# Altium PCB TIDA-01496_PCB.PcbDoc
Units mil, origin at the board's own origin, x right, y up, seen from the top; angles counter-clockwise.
Board outline 2187.5 x 2187.5 mil, 2 copper layers (Top Layer, Bottom Layer), stack 62 mil thick; 30 components, 21 nets, 107 pads, 21 vias.
Unrouted connection lines stored in the file: 1.
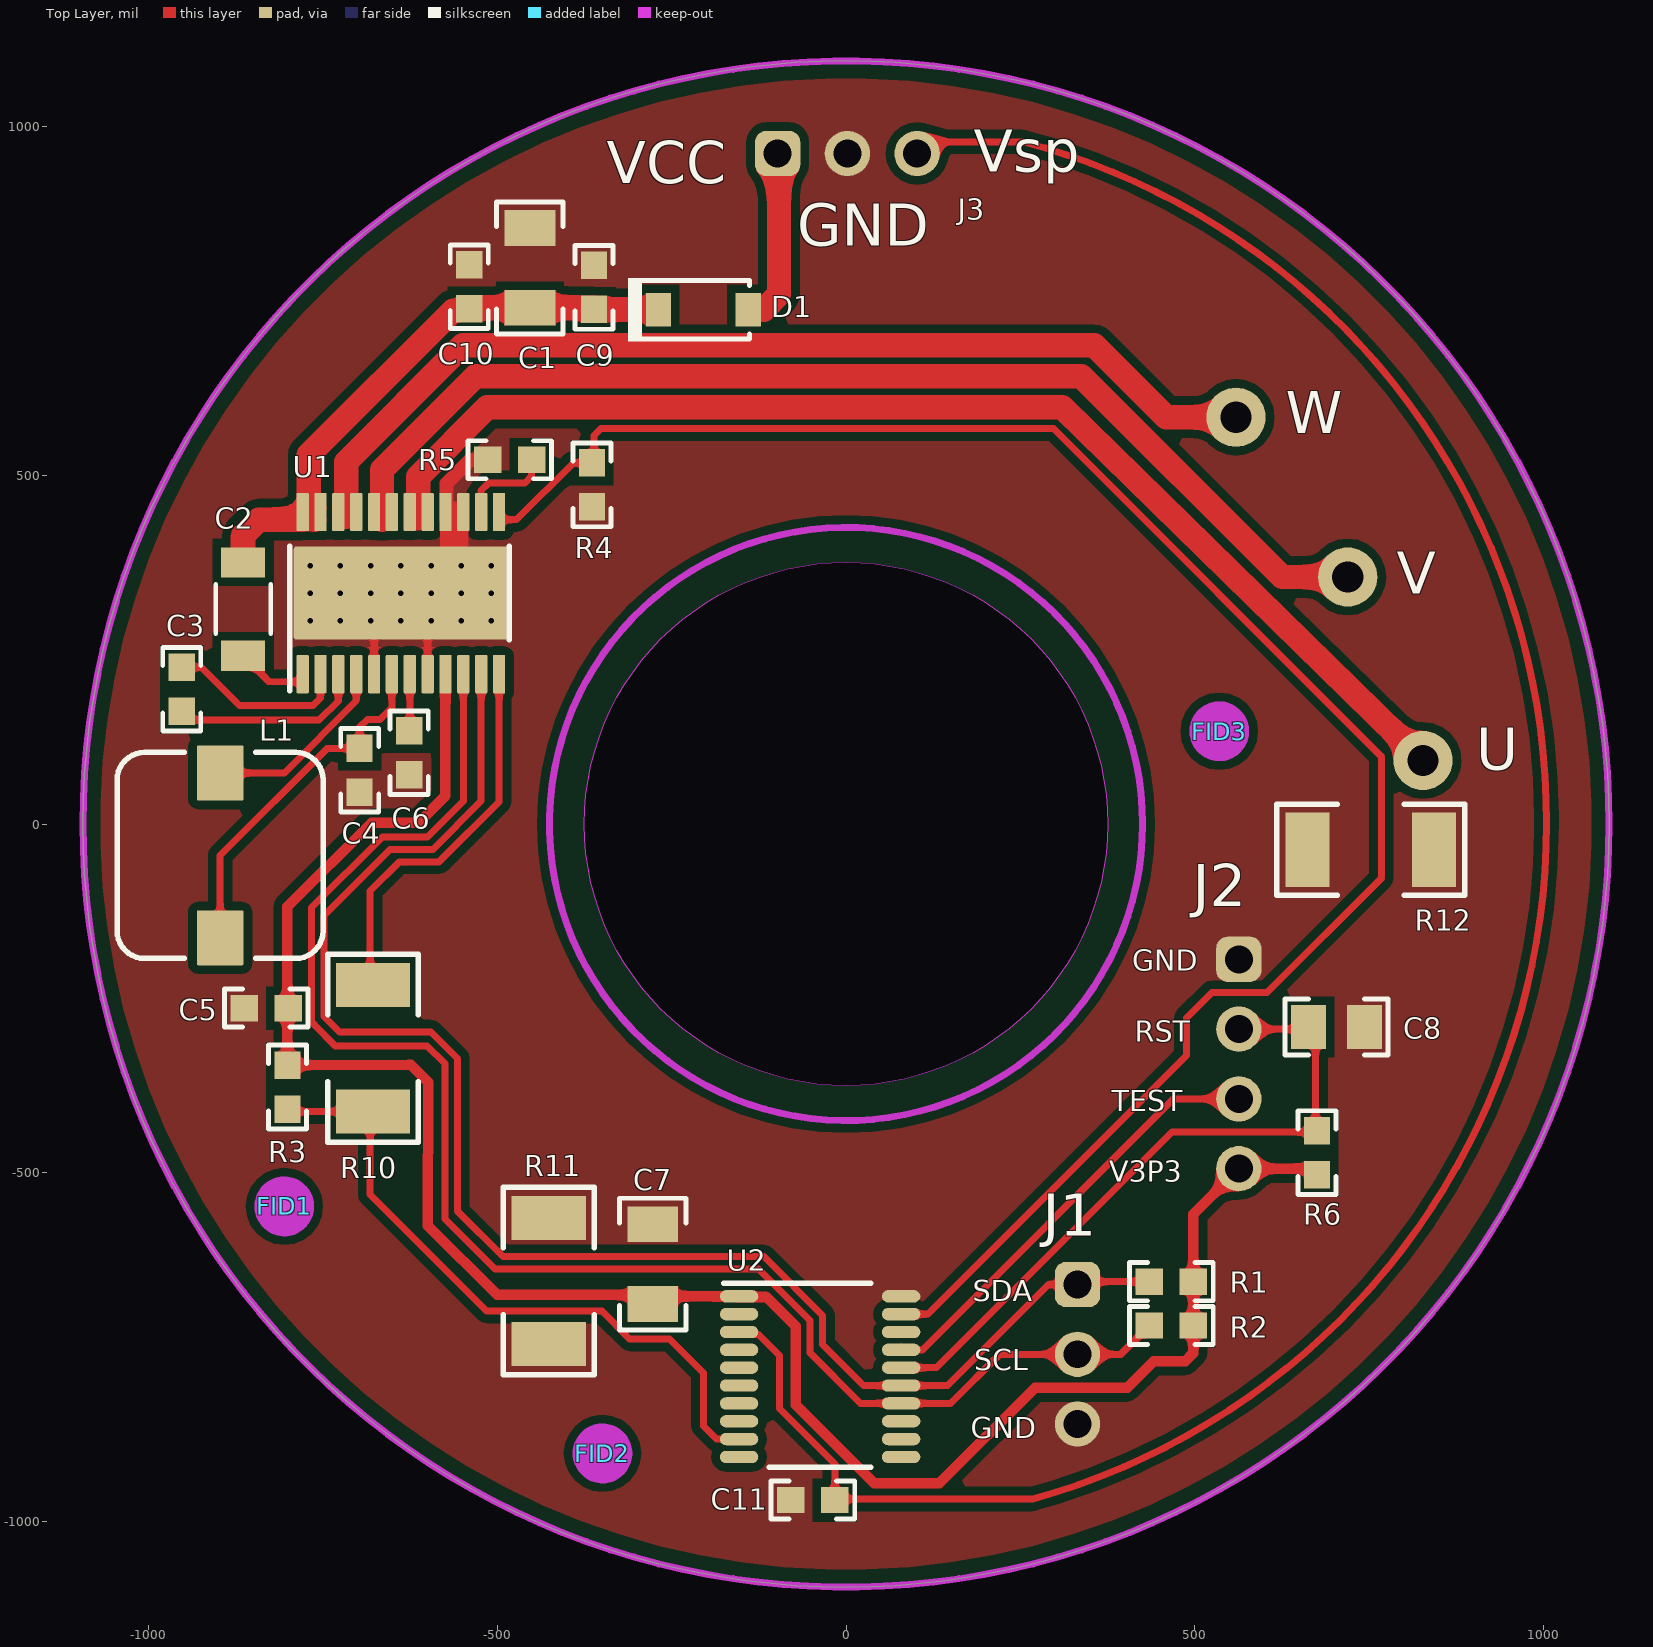
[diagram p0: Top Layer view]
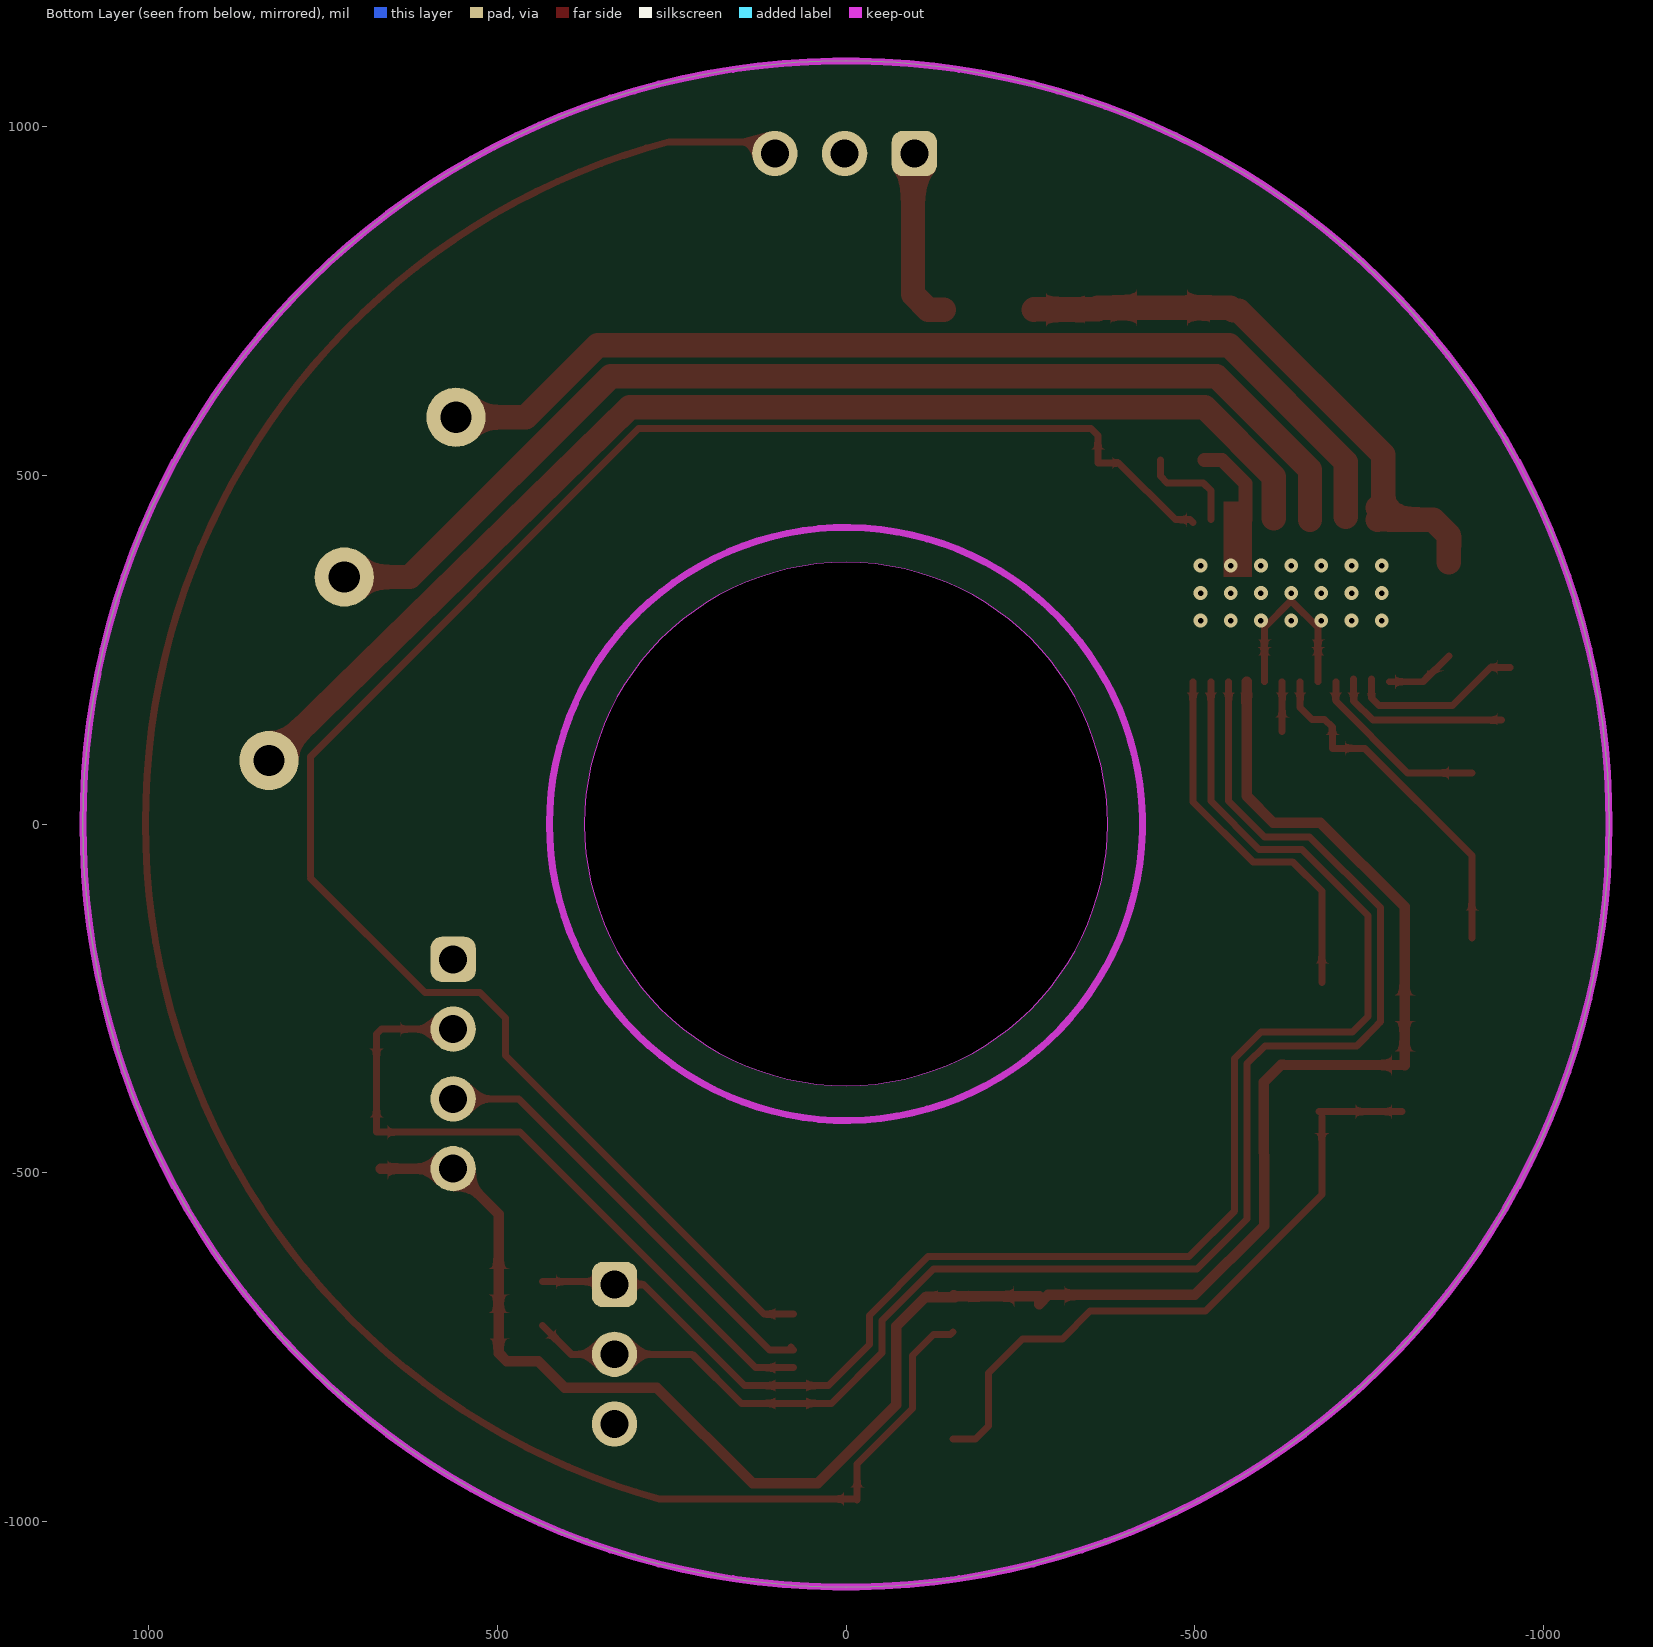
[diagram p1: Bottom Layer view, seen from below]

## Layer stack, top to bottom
Top Solder: solder mask 0.4, Solder Resist, Dk 3.5
Top Layer: signal copper 2.8
Dielectric1: core 59.2, FR-4, Dk 4.8
Bottom Layer: signal copper (thickness not stored)

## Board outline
0,-1093.75 cw(c0,0) -1093.75,0 cw(c0,0) 0,1093.75 cw(c0,0) 1093.75,0 cw(c0,0)
cut-out: 0,375 cw(c0,0) 375,0 cw(c0,0) 0,-375 cw(c0,0) -375,0 cw(c0,0)

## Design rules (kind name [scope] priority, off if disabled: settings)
AcuteAngle [All] p1: minimum=4.50000000000000E+0001 checktracksonly=FALSE
AssemblyTestPointUsage [All] p1: valid=2
BoardOutlineClearance BoardOutlineClearance_MountingHoles [OnCopper and InComponentClass('Mounting Holes')] p1: gap=40 ignorepadtopadclearanceinfootprint=FALSE
BoardOutlineClearance BoardOutlineClearance_Poly [OnCopper and IsPoly] p2: gap=25 ignorepadtopadclearanceinfootprint=FALSE
BoardOutlineClearance [OnCopper and Not InComponentClass('Logo') and not InComponentClass('FiducialMark') and not InRegion(1000,500,4000,800) and not InPoly] p3: gap=40 ignorepadtopadclearanceinfootprint=FALSE
Clearance Clearance_Keepouts [((IsTrack Or IsArc) And Not InPoly) And IsFree and IsKeepOut vs ((IsTrack Or IsArc) And Not InPoly) And IsFree and IsKeepOut] p1: gap=0 ignorepadtopadclearanceinfootprint=FALSE
Clearance Clearance_Poly [InPolygon] p2: gap=12 ignorepadtopadclearanceinfootprint=FALSE except(0: Arc-Hole Track-Hole SMDPad-Hole THPad-Hole Via-Hole Fill-Hole Poly-Hole Region-Hole Text-Hole)
Clearance [All] p3: gap=7 ignorepadtopadclearanceinfootprint=FALSE except(0: Arc-Hole Track-Hole SMDPad-Hole THPad-Hole Via-Hole Fill-Hole Poly-Hole Region-Hole Text-Hole)
ComponentClearance ComponentClearance_MountingHoles_FiducialMarks [InComponentClass('Mounting Holes') vs InComponentClass('FiducialMark')] p1: gap=50 collisioncheckmode=3 verticalgap=10 showdistances=FALSE
ComponentClearance ComponentClearance_Shunt [InComponentClass('Header') vs InComponentClass('Shunt')] p2: gap=0 collisioncheckmode=3 verticalgap=0 showdistances=FALSE
ComponentClearance ComponentClearance_Logo [InComponentClass('Logo')] p3: gap=50 collisioncheckmode=3 verticalgap=10 showdistances=FALSE
ComponentClearance ComponentClearance_ScrewToNut [(HasFootprint('NY PMS 440 0025 PH')) vs (HasFootprint('Keystone_1902C'))] p4: gap=5 collisioncheckmode=3 verticalgap=10 showdistances=FALSE
ComponentClearance ComponentClearance_MountingHoles [InComponentClass('Mounting Holes')] p5: gap=250 collisioncheckmode=3 verticalgap=100000 showdistances=FALSE
ComponentClearance ComponentClearance_SmallPassives [HasFootprint('0201*') or HasFootprint('0402*') or HasFootprint('0508') or HasFootprint('0603*') or HasFootprint('0612') or HasFootprint('0805*') or HasFootprint('0815*') or HasFootprint('0830*') or HasFootprint('1206*') or HasFootprint('1210*') or HasFootprint('1808*') or HasFootprint('1812*') or HasFootprint('1825*') or HasFootprint('2010*') or HasFootprint('2220*') or HasFootprint('2225*') or HasFootprint('2512*') or HasFootprint('2728*') or HasFootprint('3518*') vs HasFootprint('0201*') or HasFootprint('0402*') or HasFootprint('0508') or HasFootprint('0603*') or HasFootprint('0612') or HasFootprint('0805*') or HasFootprint('0815*') or HasFootprint('0830*') or HasFootprint('1206*') or HasFootprint('1210*') or HasFootprint('1808*') or HasFootprint('1812*') or HasFootprint('1825*') or HasFootprint('2010*') or HasFootprint('2220*') or HasFootprint('2225*') or HasFootprint('2512*') or HasFootprint('2728*') or HasFootprint('3518*')] p6: gap=14.96 collisioncheckmode=3 verticalgap=10 showdistances=FALSE
ComponentClearance ComponentClearance_THtoSMT [IsThruComponent vs IsSMTComponent] p7: gap=40 collisioncheckmode=3 verticalgap=30 showdistances=FALSE
ComponentClearance ComponentClearance_THtoTH [IsThruComponent vs IsThruComponent] p8: gap=30 collisioncheckmode=3 verticalgap=30 showdistances=FALSE
ComponentClearance [All] p9: gap=30 collisioncheckmode=3 verticalgap=10 showdistances=FALSE
DiffPairsRouting [All] p1: maxlimit=100 minlimit=10 mostfreqgap=10 toplayer_minwidth=15 toplayer_maxwidth=15 toplayer_prefwidth=15 bottomlayer_minwidth=15 bottomlayer_maxwidth=15 bottomlayer_prefwidth=15 maxuncoupledlength=1000
FabricationTestPointUsage TestPointUsage [All] p1: valid=2 allowmultiple=FALSE
FabricationTestpoint Testpoint [All] p1: side=3 testpointundercomponent=TRUE minsize=40 maxsize=100 preferedsize=60 minholesize=0 maxholesize=40 preferedholesize=32 testpointgrid=1 allowsidetop=TRUE allowsidebottom=TRUE usegrid=TRUE gridtolerance=0.01
FanoutControl Fanout_LCC [IsLCC] p1: bgadir=Out bgaviamode=Centered fanoutstyle=Auto fanoutdirection=Alternating viagrid=1 // Fanout_LCC (Default Rule)
FanoutControl Fanout_BGA [IsBGA] p2: bgadir=Out bgaviamode=Centered fanoutstyle=Auto fanoutdirection=Alternating viagrid=1 // Fanout_BGA (Default Rule)
FanoutControl Fanout_Default [All] p4: bgadir=Out bgaviamode=Centered fanoutstyle=Auto fanoutdirection=Alternating viagrid=1 // Fanout_Default (Default Rule)
FanoutControl Fanout_Small [(CompPinCount < 5)] p5: bgadir=Out bgaviamode=Centered fanoutstyle=Auto fanoutdirection=OutThenIn viagrid=1 // Fanout_Small (Default Rule)
HoleSize [All] p1: absolutevalues=TRUE maxlimit=251 minlimit=7.87 maxpercent=80.000 minpercent=20.000
MinimumAnnularRing MinimumAnnularRing_ThermalPadVias [IsVia and InAnyComponent] p1: minimumring=5.91
MinimumAnnularRing [All] p2: minimumring=8
MinimumSolderMaskSliver MinimumSolderMaskSliver_Logo [InComponentClass('Logo') vs InComponentClass('Logo')] p1: minsoldermaskwidth=0.7
MinimumSolderMaskSliver [All] p2: minsoldermaskwidth=3.9
PlaneConnect [All] p1: planeconnectstyle=Relief reliefexpansion=10 reliefentries=4 reliefconductorwidth=10 reliefairgap=10
PolygonConnect PolygonConnect_4 [All vs IsNamedPolygon('TOP_LAYER_GND_P008')] p1: connectstyle=Direct reliefconductorwidth=10 reliefentries=4 polygonreliefangle="90 Angle" airgapwidth=10
PolygonConnect PolygonConnect_3 [All vs IsNamedPolygon('TOP_LAYER_GND_P008')] p2: connectstyle=Direct reliefconductorwidth=10 reliefentries=4 polygonreliefangle="90 Angle" airgapwidth=10
PolygonConnect PolygonConnect_2 [All vs IsNamedPolygon('TOP_LAYER_GND_P008')] p3: connectstyle=Direct reliefconductorwidth=10 reliefentries=4 polygonreliefangle="90 Angle" airgapwidth=10
PolygonConnect PolygonConnect_1 [All vs IsNamedPolygon('TOP_LAYER_GND_P008')] p4: connectstyle=Direct reliefconductorwidth=10 reliefentries=4 polygonreliefangle="90 Angle" airgapwidth=10
PolygonConnect [All] p5: connectstyle=Relief reliefconductorwidth=10 reliefentries=4 polygonreliefangle="90 Angle" airgapwidth=10
RoutingVias ThermalPadVias [IsVia and InAnyComponent] p1: holewidth=7.87 width=19.68 viastyle="Through Hole" minholewidth=7.87 minwidth=19.68 maxholewidth=12.99 maxwidth=23.62
RoutingVias [All] p2: holewidth=16 width=34 viastyle="Through Hole" minholewidth=7.87 minwidth=26 maxholewidth=40 maxwidth=65
SilkToBoardRegionClearance [Not ((IsComment or IsDesignator) And (Hide <> 'False')) and not InRegion(1000,500,4000,800)] p1:
SilkToSilkClearance SilkToSilkClearance_Pb-FreeLogo [(HasFootprint('Pb-Free_Overlay_Medium') OR HasFootprint('Pb-Free_Overlay_Small')) vs (HasFootprint('Pb-Free_Overlay_Medium') OR HasFootprint('Pb-Free_Overlay_Small'))] p1: silktosilkclearance=0
SilkToSilkClearance [All] p2: silktosilkclearance=4
SilkToSolderMaskClearance SilkToComponentPadClearance [(IsPad or IsFill or IsRegion) and InAnycomponent] p1: minsilkscreentomaskgap=3.5 clearancetoexposedcopper=TRUE
SilkToSolderMaskClearance "Silk to Solder Mask Opening" [All] p2: minsilkscreentomaskgap=4 clearancetoexposedcopper=FALSE
SolderMaskExpansion [All] p1: expansion=1.97
Width [All] p1: maxlimit=100 minlimit=6 preferedwidth=10 checkconnectedcopper=TRUE
15 further rules are at their usual default settings.

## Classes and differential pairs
component class Header: J1 J2 J3
component class TIDA-01496_Hardware: !PCB FID1 FID2 FID3
component class FiducialMark: FID1 FID2 FID3
component class TIDA-01496: C1 C2 C3 C4 C5 C6 C7 C8 C9 C10 C11 D1 J1 J2 J3 L1 R1 R2 R3 R4 R5 R6 R10 R11 R12 U1 U2

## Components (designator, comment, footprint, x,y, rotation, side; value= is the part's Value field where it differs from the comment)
C1 "Capacitor" 1206 -453,797 r90 top value=10uF
C2 "Capacitor" 1206_180 -864,308 r270 top value=0.1uF
C3 "Capacitor" 0603 -952,193 r270 top value=0.01uF
C4 "Capacitor" 0603 -697,77 r270 top value=10uF
C5 "Capacitor" 0603 -831,-264 r0 top value=1uF
C6 "Capacitor" 0603 -626,102 r90 top value=1uF
C7 "Capacitor" 1206 -277,-630.91 r90 top value=0.1uF
C8 "Capacitor" 0805_HV 703,-291 r0 top value=2200pF
C9 "Capacitor" 0603 -361,769 r90 top value=0.1uF
C10 "Capacitor" 0603 -540,770 r90 top value=10uF
C11 "Capacitor" 0603 -47.5,-969 r180 top value=470pF
D1 "DIODE_SCHOTTKY" SOD-123FL -204.47,737 r0 top value=30V
FID1 "Fiducial" Fiducial6.4-20 -805,-548 r0 top
FID2 "Fiducial" Fiducial6.4-20 -349,-902 r0 top
FID3 "Fiducial" Fiducial6.4-20 535.01,132.9 r0 top
J1 "TSW-103-07-G-S" TSW-103-07-G-S 331.8,-760 r270 top
J2 "TSW-104-07-G-S" TSW-104-07-G-S 563,-344 r270 top
J3 "TSW-103-07-G-S" TSW-103-07-G-S 2,961 r0 top
L1 "784777470" WE-PDA_7345 -897,-45 r90 top value=47uH
R1 "Resistor" 0603 466.31,-656 r0 top value=4.75k
R2 "Resistor" 0603 466.31,-719 r0 top value=4.75k
R3 "Resistor" 0603 -800.5,-376.99 r90 top value=4.75k
R4 "Resistor" 0603 -364,486 r90 top value=4.75k
R5 "Resistor" 0603 -482,522 r0 top value=4.75k
R6 "Resistor" 0603 675,-471 r270 top value=47k
R10 "Resistor" 2010 -678,-321.55 r270 top value=0
R11 "Resistor" 2010 -426,-655 r90 top value=0
R12 "Resistor" 2010 752,-37 r180 top value=0
U1 "DRV10983SQPWPRQ1" PWP0024B_N -638,331 r90 top
U2 "MSP430G2553IPW0RQ1" PW0020A_N -37.14,-792.02 r0 top

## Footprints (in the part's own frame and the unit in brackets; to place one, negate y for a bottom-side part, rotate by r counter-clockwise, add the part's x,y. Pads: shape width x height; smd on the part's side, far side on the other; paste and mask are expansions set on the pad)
0603 [mm] "0603 from SM-752 data"
  rect 1x0.95 smd: 1(-0.8,0) 2(0.8,0)
  silkscreen extent -1.52,-0.69 1.52,0.69, body extent -0.87,-0.47 0.87,0.47, height 1
0805_HV [mil] "0805 with 30mil clearance between pads"
  rect 50x63 smd: 1(-40,0) 2(40,0)
  silkscreen extent -74,-40 74,40, body extent -43,-29 43,29, height 57
1206 [mm] "1206 from SM-752 data"
  rect 1.3x1.85 smd: 1(-1.45,0) 2(1.45,0)
  silkscreen extent -2.4,-1.21 2.4,1.21, body extent -1.7,-0.9 1.7,0.9, height 1.35
1206_180 [mm] "1206_180"
  rect 1.1x1.6 smd: 1(-1.7,0) 2(1.7,0)
  silkscreen extent -0.9,-1 0.9,1, body extent -1.75,-0.95 1.75,0.95, height 1.8
2010 [mm] "Chip Capacitor, Body 5.08x2.54mm, IPC Medium Density"
  rect 1.6x2.7 smd: 1(-2.3,0) 2(2.3,0)
  silkscreen extent -3.42,-1.65 3.42,1.65, body extent -2.73,-1.45 2.73,1.45, height 1.66
Fiducial6.4-20 [mil]
  round 25 smd mask+26.87: 1(0,0)
  Top Layer keep-out circle w46.37: c0,0 r19.68
PW0020A_N [mm] "TSOP, 20-Leads, Body 6.5x4.4mm, Pitch 0.65mm, IPC Medium Density"
  oval 1.4x0.45 smd: 1(-2.95,2.925) 2(-2.95,2.275) 3(-2.95,1.625) 4(-2.95,0.975) 5(-2.95,0.325) 6(-2.95,-0.325) 7(-2.95,-0.975) 8(-2.95,-1.625) 9(-2.95,-2.275) 10(-2.95,-2.925) 11(2.95,-2.925) 12(2.95,-2.275) 13(2.95,-1.625) 14(2.95,-0.975) 15(2.95,-0.325) 16(2.95,0.325) 17(2.95,0.975) 18(2.95,1.625) 19(2.95,2.275) 20(2.95,2.925)
  Top Overlay keep-out lines w0.2: -1.85,-3.3 1.85,-3.3
  silkscreen extent -3.5,-3.3 1.85,3.4, body extent -3.21,-3.25 3.21,3.25, height 1
PWP0024B_N [mm] "TSOP, 24-Leads, Body 7.9x4.5mm (max), Pitch 0.65mm, IPC Medium Density"
  rrect22% 1.4x0.45 smd: 1(-2.95,3.575) 2(-2.95,2.925) 3(-2.95,2.275) 4(-2.95,1.625) 5(-2.95,0.975) 6(-2.95,0.325) 7(-2.95,-0.325) 8(-2.95,-0.975) 9(-2.95,-1.625) 10(-2.95,-2.275) 11(-2.95,-2.925) 12(-2.95,-3.575) 13(2.95,-3.575) 14(2.95,-2.925) 15(2.95,-2.275) 16(2.95,-1.625) 17(2.95,-0.975) 18(2.95,-0.325) 19(2.95,0.325) 20(2.95,0.975) 21(2.95,1.625) 22(2.95,2.275) 23(2.95,2.925) 24(2.95,3.575)
  rrect6% 3.4x7.8 smd paste-2 mask-2: 25(0,0)
  rrect4% 2.4x5.16 on Top Paste: 25(0,0)
  rrect4% 2.4x5.16 on Top Solder: 25(0,0)
  silkscreen extent -3.55,-3.95 1.7,4.05, body extent -3.21,-3.9 3.21,3.9, height 1.2
SOD-123FL [mm] "Copied from SOD-123"
  rect 0.915x1.22 smd: 1(-1.637,0) 2(1.637,0)
  silkscreen extent -2.74,-1.16 1.68,1.16, body extent -1.9,-0.9 1.9,0.9, height 1
TSW-103-07-G-S [mm] "Samtec 100mil, 1x3, 230 mil above insulator"
  rrect50% 1.65x1.65 hole 1.016: 1(-2.54,0)
  round 1.65 hole 1.016: 2(0,0) 3(2.54,0)
  body extent -3.81,-1.27 3.81,1.27, height 8.38
TSW-104-07-G-S [mm] "Samtec 100mil, 1x4, 230 mil above insulator"
  rrect50% 1.65x1.65 hole 1.016: 1(-3.81,0)
  round 1.65 hole 1.016: 2(-1.27,0) 3(1.27,0) 4(3.81,0)
  body extent -5.08,-1.27 5.08,1.27, height 8.38
WE-PDA_7345 [mm] "SMD, 2-Leads, Body 7.3x7.3mm"
  rrect6% 2x1.7 smd: 1(-3,0) 2(3,0)
  silkscreen extent -3.75,-3.75 3.75,3.75, body extent -3.65,-3.65 3.65,3.65, height 4.05

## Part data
C1: library part CMP-0008785-2, "CAP, CERM, 10 uF, 50 V, +/- 20%, X5R, AEC-Q200 Grade 3, 1206", Cap_Case=1206, Manufacturer=TDK, PartNumber=CGA5L3X5R1H106M160AB, Supplier Part Number 1=445-12883-1-ND, TempCo=X5R, Tolerance_%=20%, Value1=Unknown, Value2=50V, ValueDisplayed=10uF
C2: library part CMP-0064950-2, "CAP, CERM, 0.1 uF, 25 V,+/- 5%, C0G/NP0, 1206", Cap_Case=1206, Manufacturer=MuRata, PartNumber=GRM31C5C1E104JA01L, Supplier Part Number 1=490-1767-1-ND, TempCo=C0G/NP0, Tolerance_%=5%, Value1=Unknown, Value2=25V, ValueDisplayed=0.1uF
C3: library part CMP-0006854-4, "CAP, CERM, 0.01 uF, 50 V, +/- 10%, X7R, 0603", Cap_Case=0603, Manufacturer=Kemet, PartNumber=C0603C103K5RACTU, Supplier Part Number 1=399-1091-1-ND, TempCo=X7R, Tolerance_%=10%, Value1=Unknown, Value2=50V, ValueDisplayed=0.01uF
C4: library part CMP-0007023-4, "CAP, CERM, 10 uF, 10 V, +/- 10%, X6S, 0603", Cap_Case=0603, Manufacturer=TDK, PartNumber=C1608X6S1A106M080AC, Supplier Part Number 1=445-9019-1-ND, TempCo=X6S, Tolerance_%=10%, Value1="0.004639 ohm", Value2=10V, ValueDisplayed=10uF
C5 C6: library part CMP-0007302-5, "CAP, CERM, 1 uF, 6.3 V, +/- 10%, X5R, 0603", Cap_Case=0603, Manufacturer=MuRata, PartNumber=GRM188R60J105KA01D, Supplier Part Number 1=490-1550-1-ND, TempCo=X5R, Tolerance_%=10%, Value1=Unknown, Value2=6.3V, ValueDisplayed=1uF
C7: library part CMP-0008586-2, "CAP, CERM, 0.1 uF, 50 V, +/- 10%, X7R, 1206", Cap_Case=1206, Manufacturer=Kemet, PartNumber=C1206C104K5RACTU, Supplier Part Number 1=399-1249-1-ND, TempCo=X7R, Tolerance_%=10%, Value1="0.059 ohm", Value2=50V, ValueDisplayed=0.1uF
C8: library part CMP-0007601-2, "CAP, CERM, 2200 pF, 50 V, +/- 5%, C0G/NP0, 0805", Cap_Case=0805, Manufacturer=AVX, PartNumber=08055A222JAT2A, Supplier Part Number 1=478-1330-1-ND, TempCo=C0G/NP0, Tolerance_%=5%, Value1="0.08 ohm", Value2=50V, ValueDisplayed=2200pF
C9: library part CMP-0006802-4, "CAP, CERM, 0.1 uF, 50 V, +/- 10%, X7R, 0603", Cap_Case=0603, Manufacturer=AVX, PartNumber=06035C104KAT2A, Supplier Part Number 1=478-5052-1-ND, TempCo=X7R, Tolerance_%=10%, Value1=Unknown, Value2=50V, ValueDisplayed=0.1uF
C10: library part CMP-0007007-5, "CAP, CERM, 10 uF, 25 V, +/- 20%, X5R, 0603", Cap_Case=0603, Manufacturer=TDK, PartNumber=C1608X5R1E106M080AC, Supplier Part Number 1=445-9015-1-ND, TempCo=X5R, Tolerance_%=20%, Value1="0.004639 ohm", Value2=25V, ValueDisplayed=10uF
C11: library part CMP-0006790-4, "CAP, CERM, 470 pF, 50 V, +/- 5%, C0G/NP0, 0603", Cap_Case=0603, Manufacturer=AVX, PartNumber=06035A471JAT2A, Supplier Part Number 1=478-1183-1-ND, TempCo=C0G/NP0, Tolerance_%=5%, Value1="0.063 ohm", Value2=50V, ValueDisplayed=470pF
D1: library part CMP-0028770-1, "Diode, Schottky, 30 V, 2 A, AEC-Q101, SOD-123FL", Manufacturer="ON Semiconductor", PartNumber=MBR230LSFT1G, Supplier Part Number 1=MBR230LSFT1GOSCT-ND, Value1=2A, Value2=0.43V
FID1 FID2 FID3: library part CMP-0077181-1, "Fiducial mark.  There is nothing to buy or mount.", Manufacturer=N/A
J1 J3: library part CMP-0075407-2, "Header, 100mil, 3x1, Gold, TH", Color=Black, Current_A=6.3A, Manufacturer=Samtec, Supplier Part Number 1=SAM1029-03-ND, Voltage_V=550V
J2: library part CMP-0075409-2, "Header, 100mil, 4x1, Gold, TH", Color=Black, Current_A=6.3A, Manufacturer=Samtec, Supplier Part Number 1=SAM1029-04-ND, Voltage_V=550V
L1: library part CMP-0078174-2, "Inductor, Shielded, Ferrite, 47 µH, 1.15 A, .3 ohm, AEC-Q200 Grade 1, SMD", Manufacturer="Wurth Elektronik", Supplier Part Number 1=732-6761-1-ND, Value1=".3 ohm", Value2=1.15A, ValueDisplayed=47µH
R1 R2 R3 R4 R5: library part CMP-0022456-4, "RES, 4.75 k, 1%, 0.1 W, AEC-Q200 Grade 0, 0603", Manufacturer=Vishay-Dale, PartNumber=CRCW06034K75FKEA, Power_W=100mW, Supplier Part Number 1=541-4.75KHCT-ND, TempCo="100 ppm/C", Tolerance_%=1%, Value2=0.1W, Value_Code=4k75, ValueDisplayed=4.75k
R6: library part CMP-0025814-4, "RES, 47 k, 5%, 0.1 W, AEC-Q200 Grade 0, 0603", Manufacturer=Vishay-Dale, PartNumber=CRCW060347K0JNEA, Power_W=100mW, Supplier Part Number 1=541-47KGCT-ND, TempCo="200 ppm/C", Tolerance_%=5%, Value2=0.1W, Value_Code=47k0, ValueDisplayed=47k
R10 R11 R12: library part CMP-0016044-3, "RES, 0, 5%, 0.75 W, AEC-Q200 Grade 0, 2010", Manufacturer=Vishay-Dale, PartNumber=CRCW20100000Z0EF, Power_W=750mW, Supplier Part Number 1=541-0.0WCT-ND, TempCo=ppm/C, Tolerance_%=5%, Value2=0.75W, Value_Code=0000, ValueDisplayed=0
U1: library part CMP-0065210-4, "Automotive, Three-Phase, Sensorless BLDC Motor Driver, PWP0024B (TSSOP-24)", Alternate Manufacturer="Texas Instruments"
U2: library part CMP-0081287-1, "MSP430(TM) Ultra-Low-Power Microcontrollers for Automotive Applications, PW0020A (TSSOP-20)", Alternate Manufacturer="Texas Instruments"

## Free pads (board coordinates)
  round 85 hole 45: 5(559,583) 6(719,354) 7(827,91)

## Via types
v1: diameter 19.68, hole 7.87, Top Layer to Bottom Layer, 15 vias
v2: diameter 19.68, hole 7.87, Top Layer to Bottom Layer, tented both sides, 6 vias

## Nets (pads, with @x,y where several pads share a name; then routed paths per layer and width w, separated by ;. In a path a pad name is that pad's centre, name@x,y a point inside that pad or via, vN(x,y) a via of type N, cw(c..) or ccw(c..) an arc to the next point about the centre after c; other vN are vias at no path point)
DIR: R5.2 U1.14 | length 146.3
  Top Layer w10: U1.14@-522.84,436.14 -522.84,478.16 -512,489 -460,489 -450.5,498.5 R5.2
FG: R3.1 R10.2 U2.9 | length 949.6
  Top Layer w10: R3.1@-797,-411.99 -796.89,-412.1 R10.2 ; R10.2@-682,-419 -682,-531 -515,-698 -350,-698 -310,-738 -252.79,-738 -204.13,-786.66 -204.13,-862.87 -185.41,-881.59 U2.9
GND: C1.2 C4.2 C5.1 C6.1 C7.2 C8.2 C9.2 C10.2 C11.2 J1.3 J2.1 J3.2 R4.1 R5.1 R11.1 R11.2 R12.1 R12.2 U1.5 U1.8 U1.15 U1.16 U1.25@-638,331 U2.20 | length 389.5
  Top Layer w10: U1.5@-676.39,203.86 -676.39,281.61 -638,320 -599.61,281.61 U1.8@-599.61,203.86
  Top Layer w20: U1.16@-572.88,436.14 -572.88,488.09 -538.97,522 R5.1
  other v1: -724.61,291.63 -681.31,291.63 -638,291.63 -594.69,291.63 -551.39,291.63 -724.61,331 -681.31,331 -638,331 -594.69,331 -551.39,331 -724.61,370.37 -681.31,370.37 -638,370.37 -594.69,370.37 -551.39,370.37
  other v2: -767.92,291.63 -508.08,291.63 -767.92,331 -508.08,331 -767.92,370.37 -508.08,370.37
NetC2_2: C2.2 U1.1 | length 100.7
  Top Layer w10: C2.2 -826.79,203.86 U1.1@-778.75,203.86
NetC3_1: C3.1 U1.2 | length 252.9
  Top Layer w10: C3.1 -923.5,224.5 -869,170 -764,170 -753.16,180.84 U1.2@-753.16,207.8
NetC3_2: C3.2 U1.3 | length 254.7
  Top Layer w10: C3.2@-939.5,149 -755,149 -727.57,176.43 U1.3@-727.57,207.8
NetC4_1: C4.1 L1.1 U1.6 | length 506.7
  Top Layer w10: L1.1 -897,-45 -743.5,108.5 C4.1 -697,139 -686,150 -668,150 -650.8,167.2 U1.6@-650.8,203.86
NetC6_2: C6.2 U1.7 | length 71.5
  Top Layer w10: U1.7@-625.2,203.86 -625,203.65 C6.2@-625,132.45
NetL1_2: L1.2 U1.4 | length 265.5
  Top Layer w10: L1.2 -804.89,73.11 -701.98,176.02 U1.4@-701.98,203.86
NetR10_1: R10.1 U1.12 | length 540.8
  Top Layer w10: R10.1@-682,-227 -682,-96 -640.12,-54.12 -583.12,-54.12 -497.25,31.75 U1.12@-497.25,203.86
"PHASE U": pad.7 U1.17 U1.18 | length 1747.4
  Top Layer w35: -613.2,438.14 -613.2,497.8 -514,597 310,597 pad.7
"PHASE V": pad.6 U1.19 U1.20 | length 1631
  Top Layer w35: -665,435.76 -665,508 -531,642 337,642 625,354 pad.6
"PHASE W": pad.5 U1.21 U1.22 | length 1465.7
  Top Layer w35: -716.18,440.18 -716.18,518.82 -549,686 356,686 459,583 pad.5
RESET: C8.1 J2.2 R6.1 U2.16 | length 990.9
  Top Layer w10: U2.16@75.28,-779.23 U2.16 129.41,-779.23 466.99,-441.65 672.86,-441.65 672.86,-300.86 666,-294 J2.2
SCL: J1.2 R2.1 U1.10 U2.14 | length 2273.7
  Top Layer w10: U1.10@-548.43,203.86 -548.43,32.7 -599.5,-18.37 -664.37,-18.37 -765.87,-119.87 -765.87,-283.4 -761.9,-287.38 -761.9,-288.1 -732,-318 -600.28,-318 -575,-343.28 -575,-566 -503,-638 -125.22,-638 -51.63,-711.59 -51.63,-757.85 20.93,-830.41 U2.14 150,-830.41 220.41,-760 J1.2 393.81,-760 R2.1 ; J1.2@331.8,-756 321.8,-756 332.8,-745 J1.2@333.8,-746
SDA: J1.1 R1.1 U1.11 U2.15 | length 2227.3
  Top Layer w10: U1.11@-522.84,203.86 -522.84,33.01 -592.1,-36.25 -653.25,-36.25 -748,-131 -748,-276 -726,-298 -595,-298 -557,-336 -557,-381 -557.13,-554.87 -491.87,-620.13 -117.81,-620.13 -33.75,-704.19 -33.75,-746.25 24.82,-804.82 U2.15 145.18,-804.82 290,-660 J1.1 ; J1.1@332.8,-645 343.8,-656 R1.1
SPEED: R4.2 U1.13 U2.19 | length 2691.7
  Top Layer w10: U1.13@-497.25,432.2 -493.31,436.14 -472.12,436.14 -390.77,517.5 R4.2 -361,517.5 -361,557 -351.37,566.63 297.42,566.63 767.14,96.9 767.14,-74.86 ; U2.19@75.28,-702.46 U2.19 117.54,-702.46 488,-332 488,-278 524.35,-241.65 603.35,-241.65 767.14,-77.86
"SPEED CONTROL": C11.1 J3.3 U2.3 | length 3363
  Top Layer w10: U2.3 -149.43,-731.91 -125.58,-731.91 -95.49,-762 -95.49,-837.61 -16,-917.1 C11.1 -14.42,-967.42 267.68,-967.42 ccw(c-1,1) 1004,1 ccw(c-3,4) 253.67,977.74 J3.3@118.74,977.74
TEST: J2.3 U2.17 | length 642.1
  Top Layer w10: U2.17@79.14,-749.78 75.28,-753.64 U2.17 109.36,-753.64 469,-394 J2.3
V3P3: C5.2 C7.1 J2.4 R1.2 R2.2 R3.2 R6.2 U1.9 U2.1 | length 2909.5
  Top Layer w15: U1.9@-574.02,203.86 -574.02,40.48 -612.5,2 -680,2 -800.5,-118.5 R3.2 -627,-345 -624,-345 -599,-370 -599.25,-575.75 -500,-675 -290,-675 C7.1 -277,-676.87 U2.1@-157,-676.87 ; U2.1@-154.64,-675.51 U2.1 U2.1@-157,-676.87 ; R6.2@666.5,-494 J2.4 497.8,-559.2 R2.2 497.8,-758.2 486,-770 440.85,-770 403,-807.85 270.96,-807.85 133.81,-945 40.71,-945 -72,-832.29 -72,-720.03 -113.81,-678.22 -155.64,-678.22 U2.1@-157,-676.87
VCC: C1.1 C2.1 C9.1 C10.1 D1.1 D1.2 J3.1 U1.23 U1.24 | length 1096.4
  Top Layer w35: C2.1 -864,414 -841.86,436.14 U1.24@-778.75,436.14 ; -799.1,437 -765,437 ; -765.95,448.94 U1.23@-761.8,453.09 ; U1.23@-761.8,436.14 -769.89,444.23 -769.89,529 -562.89,736 -555,736 -551,740 C9.1@-361,740 ; C9.1 -269.44,737.5 D1.1 ; D1.2 -118,737 -96,759 J3.1@-96,944
pads on no net: FID1.1 FID2.1 FID3.1 U1.25@-638,331 U2.2 U2.4 U2.5 U2.6 U2.7 U2.8 U2.10 U2.11 U2.12 U2.13 U2.18

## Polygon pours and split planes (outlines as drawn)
GND on Top Layer "TOP_LAYER_GND_P008" (solid, remove dead copper, pour order 8): 1093.75,0 cw(c0,0) 0,-1093.75 cw(c0,0) -1093.75,0 cw(c0,0) 0,1093.75 cw(c0,0)

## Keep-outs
Keep-Out Layer:
  circle w10: c0,0 r1093.75
  circle w10: c0,0 r425
  text ".Layer_Name" at -623,-2038.49 h60

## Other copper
Top Layer:
  rectangle net GND: -582,354 -541,462
  text ".Layer_Name" at -623,-2038.49 h60
Bottom Layer:
  text ".Layer_Name" at -623,-2038.49 h60

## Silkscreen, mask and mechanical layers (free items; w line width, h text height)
Top Overlay:
  text "Vsp" at 183,935 h60
  text "VCC" at -343,918 h60
  text "GND" at -70,829 h60
  text "W" at 630,560 h60
  text "V" at 789,330 h60
  text "U" at 903,78 h60
  text "GND" at 410,-210 h30
  text "RST" at 414,-312 h30
  text "TEST" at 381,-412 h30
  text "V3P3" at 377,-513 h30
  text "SDA" at 181.8,-684 h30
  text "SCL" at 183.8,-783 h30
  text "GND" at 179,-880 h30
  text ".Layer_Name" at -623,-2038.49 h60
Bottom Overlay:
  text ".Layer_Name" at -623,-2038.49 h60
Top Paste:
  text ".Layer_Name" at -623,-2038.49 h60
Bottom Paste:
  text ".Layer_Name" at -623,-2038.49 h60
Top Solder:
  text ".Layer_Name" at -623,-2038.49 h60
  text ".Layer_Name" at -623,-2038.49 h60
Bottom Solder:
  text ".Layer_Name" at -623,-2038.49 h60
Drill Guide:
  text ".Layer_Name" at -623,-2038.49 h60
M1 Board Outline:
  circle w10: c0,0 r375
  circle w10: c0,0 r1096.88
  text ".Layer_Name" at -623,-2038.49 h60
M2 Board Dimensions:
  rectangle: -1075,-1580 -700,-1455
  rectangle: -1200,-1455 -1075,-1330
  lines w7: -1200,-1455 -200,-1455 ; -1075,-1580 -1075,-1330 ; -950,-1580 -950,-1330 ; -700,-1580 -700,-1330 ; -450,-1580 -450,-1330 ; -1200,-1580 -1200,-1330 -200,-1330 -200,-1580 -1200,-1580
  text ".Layer_Name" at -623,-2038.49 h60
M3 3D STEP Top:
  text ".Layer_Name" at -623,-2038.49 h60
M4 3D STEP Bottom:
  text ".Layer_Name" at -623,-2038.49 h60
M5 Assembly Top:
  lines w10: -1492,-2110.17 5108,-2110.17 ; -1492,-1906.83 5110,-1906.83 ; -1492,-1703.5 -1492,-2313.5 2513,-2313.5 5110,-2313.5 5110,-1703.5 -1491.5,-1703.5 -1491.5,-2313.5 84,-2313.5 ; 973,-2313.5 973,-1703.5 ; 2240,-1906.83 2240,-1703.5 ; 3080,-1906.83 3080,-1703.5 ; 3702,-2320 3702,-2117.17
  text "COMPONENTS MARKED 'DNP' SHOULD NOT BE POPULATED." at -46.5,-1498.5 h60
  text "ASSEMBLY VARIANT:" at -47,-1614 h60
  text ".VariantName" at 989,-1614 h60
  text "PCB VIEWED FROM TOP SIDE" at -1428.5,-1835.67 h60
  text "BOARD #:" at 1048,-1835.67 h60
  text ".PRJ_Number" at 1593.5,-1835.67 h60
  text "REV:" at 2438,-1835.67 h60
  text ".PCB_Rev" at 2729.5,-1835.67 h60
  text "SVN REV:" at 3276,-1835.67 h60
  text ".VersionControl_RevNumber" at 3782,-1835.67 h60
  text "TID #:" at 1048,-2039 h60
  text ".TID" at 1593.5,-2039 h60
  text "PLOT NAME =" at -1428.5,-2244.34 h60
  text ".plot_File_Name" at -623,-2244.34 h60
  text "GENERATED    :" at 1050,-2244.34 h60
  text ".Print_Date" at 1919.5,-2244.34 h60
  text ".Print_Time" at 2648.5,-2244.34 h60
  text "TEXAS INSTRUMENTS" at 3913,-2244.34 h60
M6 Assembly Bottom:
  lines w10: -1492.5,-1907.33 5109.5,-1907.33 ; -1490.5,-2110.67 5109.5,-2110.67 ; -84.5,-2320.5 -84.5,-2117.67 ; 537.5,-1907.33 537.5,-1704 ; 1377.5,-1907.33 1377.5,-1704 ; 2644.5,-2314 2644.5,-1704 ; 3533.5,-2314 5109,-2314 5109,-1704 -1492.5,-1704 -1492.5,-2314 1104.5,-2314 5109.5,-2314 5109.5,-1704
  text "COMPONENTS MARKED 'DNP' SHOULD NOT BE POPULATED." at 4902,-1498 h60
  text ".VariantName" at 3858,-1614 h60
  text "ASSEMBLY VARIANT:" at 4897,-1614 h60
  text ".VersionControl_RevNumber" at -164.5,-1836.17 h60
  text "SVN REV:" at 341.5,-1836.17 h60
  text ".PCB_Rev" at 888,-1836.17 h60
  text "REV:" at 1179.5,-1836.17 h60
  text ".PRJ_Number" at 2024,-1836.17 h60
  text "BOARD #:" at 2569.5,-1836.17 h60
  text "PCB VIEWED FROM BOTTOM SIDE" at 5046,-1836.17 h60
  text ".TID" at 2024,-2039.5 h60
  text "TID #:" at 2569.5,-2039.5 h60
  text "TEXAS INSTRUMENTS" at -295.5,-2244.84 h60
  text ".Print_Time" at 969,-2244.84 h60
  text ".Print_Date" at 1698,-2244.84 h60
  text "GENERATED    :" at 2567.5,-2244.84 h60
  text ".plot_File_Name" at 4240.5,-2244.84 h60
  text "PLOT NAME =" at 5046,-2244.84 h60
M9 Title Sheet:
  drawing of 57 lines, arcs and shapes, not listed
  text "1" at -460.16,6856.5 h70
  text "2" at 2035.5,6856.5 h70
  text "3" at 4524.84,6856.5 h70
  text "4" at 7031.51,6856.5 h70
  text "5" at 9530.5,6856.5 h70
  text "6" at 12035.5,6856.5 h70
  text "A" at -1616.5,5713.5 h70
  text "A" at 13183.5,5713.5 h70
  text "B" at -1616.5,3333.5 h70
  text "B" at 13183.5,3333.5 h70
  text "C" at -1616.5,958.5 h70
  text "C" at 13183.5,958.5 h70
  text "PROJECT TITLE:" at 10143.5,-902.5 h45
  text ".PRJ_Title" at 10193.5,-1035.83 h70
  text "DESIGNED FOR:" at 10143.5,-1203.5 h45
  text ".PRJ_Customer" at 10193.5,-1343.5 h70
  text "D" at -1616.5,-1411.5 h70
  text "D" at 13183.5,-1411.5 h70
  text "FILE NAME:" at 10143.5,-1503.5 h45
  text ".PCB_File_Name_No_Path" at 10193.5,-1623.5 h70
  text "Texas Instruments (TI) and/or its licensors do not warrant the accuracy or completeness of this specification" at 5174,-1785.34 h45
  text "ENGINEER:" at 10143.5,-1793.5 h45
  text "LAYOUT BY:" at 11648.5,-1793.5 h45
  text "or any information contained therein. TI and/or its licensors do not warrant that this design will meet" at 5129.01,-1898 h45
  text ".PRJ_Engineer" at 10193.5,-1948.49 h70
  text ".PCB_Layout" at 11699,-1948.49 h70
  text "the specifications, will be suitable for your application or fit for any particular purpose, or will operate in" at 5129.01,-2010.67 h45
  text ".Layer_Name" at -623,-2038.49 h60
  text "ALTIUM DESIGNER VERSION:" at 11648.5,-2103.5 h45
  text "an implementation. TI and/or its licensors do not warrant that the design is production worthy. You should" at 5129.01,-2123.33 h45
  text "completely validate and test your design implementation to confirm the system functionality for your application." at 5174,-2236 h45
  text ".print_Scale" at 10193.5,-2236.83 h70
  text ".Application_BuildNumber" at 11699,-2236.83 h70
  text "1" at -460.16,-2443.5 h70
  text "2" at 2035.5,-2443.5 h70
  text "3" at 4524.84,-2443.5 h70
  text "4" at 7031.51,-2443.5 h70
  text "5" at 9530.5,-2443.5 h70
  text "6" at 12035.5,-2443.5 h70
M10 Fab Notes:
  drawing of 173 lines, arcs and shapes, not listed
  text "DESIGN INFORMATION" at 11178.02,5021 h60
  text "MIN. TRACK WIDTH:" at 10533.46,4841 h60
  text "8" at 11629.7,4841 h60
  text "MIL" at 11784.46,4841 h60
  text "MIN. CLEARANCE:" at 10533.46,4709 h60
  text "0.2" at 11569.7,4709 h60
  text "mm" at 11784.46,4709 h60
  text "MIN. VIA PAD SIZE:" at 10533.46,4577 h60
  text "24" at 11599.71,4577 h60
  text "MIL" at 11784.46,4577 h60
  text "0.05mm (2MIL)" at 11228.46,4435.29 h60
  text "MINIMUM ANNULAR RING" at 10204.23,4431 h60
  text "EXTERNAL" at 11936.46,4431 h60
  text "PER" at 10404.23,4313 h60
  text "IPC-D-275 CLASS 2 LEVEL C" at 10624.23,4313 h60
  text "MIL, HOLES" at 12112.46,4200.71 h60
  text "+/-" at 11720,4200 h60
  text "+/-" at 12574,4200 h60
  text "REGISTRATION TOLERANCES:" at 10204.23,4195 h60
  text "METAL" at 11404,4195 h60
  text "5" at 11980.2,4195 h60
  text "3" at 12813.2,4195 h60
  text "MIL" at 12929.46,4195 h60
  text "+/-" at 12574,4082 h60
  text "HOLE SIZE TOLERANCE (UNLESS OTHERWISE SPECIFIED):" at 10204.23,4077 h60
  text "3" at 12813.2,4077 h60
  text "MIL" at 12929.46,4077 h60
  text "MATERIAL:" at 10129.46,3867.54 h60
  text "FR-4 High Tg" at 11115.9,3727.21 h60
  text "FR-408" at 10550.46,3718.64 h60
  text "OTHER" at 12038.46,3718.64 h60
  text "X" at 10961,3715 h60
  text "62 MIL (1.6mm) +/-10%" at 10870.56,3555.92 h60
  text "THICKNESS:" at 10204.23,3551.64 h60
  text "X" at 10742.4,3551.64 h60
  text "OTHER" at 12155.46,3551.64 h60
  text "TOLERANCE:" at 10204.23,3393.64 h60
  text "X" at 11043.53,3393.64 h60
  text "ANSI IPC-6012 TYPE 3 CLASS 2" at 11230.48,3393.64 h60
  text "OTHER +/-" at 11230.46,3237.64 h60
  text "BOW & TWIST:" at 10204.23,3080.64 h60
  text "X" at 11043.53,3080.64 h60
  text "ANSI IPC-6012 TYPE 3 CLASS 2" at 11230.48,3080.64 h60
  text "OTHER +/-" at 11230.46,2922.13 h60
  text "DRILLING:" at 10129.46,2783.64 h60
  text "REFERENCE:" at 10204.23,2666.64 h60
  text "X" at 10852.46,2666.64 h60
  text "AS SHOWN" at 11039.46,2666.64 h60
  text "X" at 11753.46,2666.64 h60
  text "NC_DRILL FILES" at 11890.46,2666.64 h60
  text "PTH COPPER THICKNESS:" at 10204.23,2508.64 h60
  text "X" at 11334.46,2508.64 h60
  text "20-30 um" at 11471.46,2508.64 h60
  text "OTHER" at 12188.46,2508.64 h60
  text "BOARD FINISH:" at 10129.46,2349.64 h60
  text "SILKSCREEN:" at 10284.68,2231.64 h60
  text "X" at 11233.46,2231.64 h60
  text "TOP" at 11359.46,2231.64 h60
  text "BOTTOM" at 11870.46,2231.64 h60
  text "SILKSCREEN COLOR:" at 10284.68,2064.64 h60
  text "X" at 11232.42,2064.64 h60
  text "WHITE" at 11359.46,2064.64 h60
  text "OTHER" at 11870.46,2064.64 h60
  text "X" at 11363.42,1905.44 h60
  text "GREEN" at 11490.46,1905.44 h60
  text "OTHER" at 12108.46,1905.44 h60
  text "SOLDER RESIST COLOR:" at 10284.68,1894.64 h60
  text "X" at 11363.42,1735.44 h60
  text "MATTE" at 11490.46,1735.44 h60
  text "SEMI-GLOSS" at 12108,1734.8 h60
  text "IMMERSION GOLD (ENIG)" at 11190.46,1546.92 h60
  text "ENEPIG" at 12528,1543.64 h60
  text "SURFACE FINISH:" at 10129.46,1542.64 h60
  text "X" at 11003.51,1542.64 h60
  text "IMM. TIN/SILVER OR EQUIV" at 10459,1385.64 h60
  text "OTHER" at 11890.46,1385.64 h60
  text "ARRAY/PANEL:" at 10129.46,1206.64 h60
  text "CUT AND TRIM PER M1 BOARD OUTLINE" at 11190.46,1202.35 h60
  text "N.C. ROUTE" at 11190.46,1050.64 h60
  text "X" at 11869.46,1050.64 h60
  text "V. SCORE" at 12056.46,1050.64 h60
  text "CERTIFICATION:" at 10129.46,913.64 h60
  text "MATERIALS AND WORKMANSHIP FOR ALL PCBS" at 10854.46,913.64 h60
  text "TO MEET OR EXCEED THE REQUIREMENTS OF:" at 10854.46,815.64 h60
  text "X" at 10480.96,679.13 h60
  text "ANSI IPC-A-600F CLASS ->" at 10619.96,679.13 h60
  text "X" at 12259.02,679.13 h60
  text "2" at 12377.96,679.14 h60
  text "1" at 12062.96,677.64 h60
  text "3" at 12731.96,677.64 h60
  text "X" at 11295.02,519.64 h60
  text "RoHS" at 11431.96,519.64 h60
  text "OTHER" at 12076.36,519.64 h60
  text "PER ORDER" at 12473.42,519.64 h60
  text "ALL BOARDS MUST MEET OR EXCEED UL94-V0 REQUIREMENTS." at 10157,354 h60
  text "PCB MUST BEAR THE UL94V-0 UL REGISTERED MATERIAL ID NUMBER" at 10157,234 h60
  text "ADDITIONAL REQUIREMENTS:" at 10129.46,60.64 h60
  text "MICROSECTION:" at 10204.23,-54.36 h60
  text "YES" at 11109.96,-54.36 h60
  text "REQUIRED" at 11971.46,-210.51 h60
  text "BARE BOARD ELEC. TEST:" at 10204.23,-213.36 h60
  text "NONE" at 11509.96,-213.36 h60
  text "X" at 11844.46,-213.36 h60
  text "PER ORDER" at 12563.46,-213.36 h60
  text ".Layer_Name" at -623,-2038.49 h60
M11 Gerber Information:
  lines w10: -1492,-2110.17 5108,-2110.17 ; -1492,-1906.83 5110,-1906.83 ; -1492,-1703.5 -1492,-2313.5 2513,-2313.5 5110,-2313.5 5110,-1703.5 -1491.5,-1703.5 -1491.5,-2313.5 84,-2313.5 ; 973,-2313.5 973,-1703.5 ; 2240,-1906.83 2240,-1703.5 ; 3080,-1906.83 3080,-1703.5 ; 3702,-2320 3702,-2117.17
  text "ALL ARTWORK VIEWED FROM TOP SIDE" at -1428.5,-1835.67 h60
  text "BOARD #:" at 1048,-1835.67 h60
  text ".PRJ_Number" at 1593.5,-1835.67 h60
  text "REV:" at 2438,-1835.67 h60
  text ".PCB_Rev" at 2729.5,-1835.67 h60
  text "SVN REV:" at 3276,-1835.67 h60
  text ".VersionControl_RevNumber" at 3782,-1835.67 h60
  text "LAYER NAME =" at -1428.5,-2038.49 h60
  text "TID #:" at 1048,-2039 h60
  text ".TID" at 1593.5,-2039 h60
  text "PLOT NAME =" at -1428.5,-2244.34 h60
  text ".plot_File_Name" at -623,-2244.34 h60
  text "GENERATED    :" at 1050,-2244.34 h60
  text ".Print_Date" at 1919.5,-2244.34 h60
  text ".Print_Time" at 2648.5,-2244.34 h60
  text "TEXAS INSTRUMENTS" at 3913,-2244.34 h60
M12 Stackup:
  lines w1: 11837,6160.32 11936.68,6260 12056.68,6380 12176.68,6500 12296.68,6620 ; 11837,6220.32 11876.68,6260 11996.68,6380 12116.68,6500 12236.68,6620 ; 11837,6280.32 11936.68,6380 12056.68,6500 12176.68,6620 ; 11837,6340.32 11876.68,6380 11996.68,6500 12116.68,6620 ; 11837,6400.32 11936.68,6500 12056.68,6620 ; 11837,6460.32 11876.68,6500 11996.68,6620 ; 11837,6520.32 11936.68,6620 ; 11837,6580.32 11876.68,6620 ; 11876.68,6140 11996.68,6260 12116.68,6380 12236.68,6500 12356.68,6620 ; 11936.68,6140 12056.68,6260 12176.68,6380 12296.68,6500 12416.68,6620 ; 11996.68,6140 12116.68,6260 12236.68,6380 12356.68,6500 12476.68,6620 ; 12056.68,6140 12176.68,6260 12296.68,6380 12416.68,6500 12536.68,6620 ; 12116.68,6140 12236.68,6260 12356.68,6380 12476.68,6500 12596.68,6620 ; 12176.68,6140 12296.68,6260 12416.68,6380 12536.68,6500 12656.68,6620 ; 12236.68,6140 12356.68,6260 12476.68,6380 12596.68,6500 12716.68,6620 ; 12296.68,6140 12416.68,6260 12536.68,6380 12656.68,6500 12776.68,6620 ; 12356.68,6140 12476.68,6260 12596.68,6380 12716.68,6500 12836.68,6620 ; 12416.68,6140 12536.68,6260 12656.68,6380 12776.68,6500 12896.68,6620 ; 12476.68,6140 12596.68,6260 12716.68,6380 12836.68,6500 12956.68,6620 ; 12536.68,6140 12656.68,6260 12776.68,6380 12896.68,6500 12956.68,6560 ; 12596.68,6140 12716.68,6260 12836.68,6380 12956.68,6500 ; 12656.68,6140 12776.68,6260 12896.68,6380 12956.68,6440 ; 12716.68,6140 12836.68,6260 12956.68,6380 ; 12776.68,6140 12896.68,6260 12956.68,6320 ; 12836.68,6140 12956.68,6260 ; 12896.68,6140 12956.68,6200
  lines w15: 8537.84,6140 8947.76,6140 9757.54,6140 10617.31,6140 11267.14,6140 11837,6140 12956.68,6140 ; 8537.84,6260 8947.76,6260 9757.54,6260 10617.31,6260 11267.14,6260 11837,6260 12956.68,6260 ; 8537.84,6380 8947.76,6380 9757.54,6380 10617.31,6380 11267.14,6380 11837,6380 12956.68,6380 ; 8537.84,6500 8947.76,6500 9757.54,6500 10617.31,6500 11267.14,6500 11837,6500 12956.68,6500 ; 8537.84,6620 12956.68,6620 ; 8947.76,6740 8947.76,6020 ; 9757.54,6740 9757.54,6020 ; 10617.31,6740 10617.31,6020 ; 11267.14,6740 11267.14,6020 ; 11837,6740 11837,6020 ; 8947.76,6020 8537.84,6020 8537.84,6740 12956.68,6740 12956.68,6020 11837,6020 ; 8947.76,6020 9757.54,6020 ; 9757.54,6020 10617.31,6020 ; 10617.31,6020 11267.14,6020 ; 11267.14,6020 11837,6020
  text "Layer" at 8597.84,6650 h60
  text "Name" at 9007.76,6650 h60
  text "Material" at 9817.54,6650 h60
  text "Thickness" at 10677.31,6650 h60
  text "Constant" at 11327.14,6650 h60
  text "Board Layer Stack" at 11897,6650 h60
  text "1" at 8597.84,6530 h60
  text "Top Overlay" at 9007.76,6530 h60
  text "2" at 8597.84,6410 h60
  text "Top Solder" at 9007.76,6410 h60
  text "Solder Resist" at 9817.54,6410 h60
  text "0.40mil" at 10677.31,6410 h60
  text "3.5" at 11327.14,6410 h60
  text "3" at 8597.84,6290 h60
  text "Top Layer" at 9007.76,6290 h60
  text "Copper" at 9817.54,6290 h60
  text "2.80mil" at 10677.31,6290 h60
  text "4" at 8597.84,6170 h60
  text "Dielectric1" at 9007.76,6170 h60
  text "FR-4" at 9817.54,6170 h60
  text "59.20mil" at 10677.31,6170 h60
  text "4.8" at 11327.14,6170 h60
  text "5" at 8597.84,6050 h60
  text "Bottom Layer" at 9007.76,6050 h60
  text "Copper" at 9817.54,6050 h60
  text ".Layer_Name" at -623,-2038.49 h60
M13 Component Bodies Top:
  text ".Layer_Name" at -623,-2038.49 h60
M14 Component Bodies Bottom:
  text ".Layer_Name" at -623,-2038.49 h60
M15 Courtyards Top:
  text ".Layer_Name" at -623,-2038.49 h60
M16 Courtyards Bottom:
  text ".Layer_Name" at -623,-2038.49 h60
Drill Drawing:
  circle w10: c4148.9,1923.54 r22.14
  lines w10: 4126.76,2001.02 4171.04,2001.02 4171.04,2045.3 4126.76,2045.3 4126.76,2001.02 ; 4126.76,2111.71 4137.83,2111.71 4148.9,2100.64 4159.97,2111.71 4171.04,2111.71 4159.97,2122.78 4171.04,2133.85 4159.97,2133.85 4148.9,2144.92 4137.83,2133.85 4126.76,2133.85 4137.83,2122.78 4126.76,2111.71
  lines w12: 4086,1871.51 7198.94,1871.51 ; 4086,2170.38 7198.94,2170.38 ; 4401.63,1771.89 4401.63,2270 ; 4718.82,1771.89 4718.82,2270 ; 5340.56,1771.89 5340.56,2270 ; 5584.88,1771.89 5584.88,2270 ; 5945.22,1771.89 5945.22,2270 ; 6654.73,1771.89 6654.73,2270 ; 4086,1771.89 7198.94,1771.89 7198.94,2270 4086,2270 4086,1771.89
  text "Symbol" at 4145.77,2200.26 h72
  text "Quantity" at 4431.52,2200.26 h72
  text "Finished Hole Size" at 4748.7,2200.26 h72
  text "Plated" at 5370.45,2200.26 h72
  text "Hole Type" at 5614.77,2200.26 h72
  text "Drill Layer Pair" at 5975.11,2200.26 h72
  text "Hole Tolerance" at 6684.62,2200.26 h72
  text "21" at 4431.52,2100.64 h60
  text "7.87mil (0.200mm)" at 4748.7,2100.64 h60
  text "PTH" at 5370.45,2100.64 h60
  text "Round" at 5614.77,2100.64 h60
  text "Top Layer - Bottom Layer" at 5975.11,2100.64 h60
  text "10" at 4431.52,2001.02 h60
  text "40.00mil (1.016mm)" at 4748.7,2001.02 h60
  text "PTH" at 5370.45,2001.02 h60
  text "Round" at 5614.77,2001.02 h60
  text "Top Layer - Bottom Layer" at 5975.11,2001.02 h60
  text "3" at 4431.52,1901.4 h60
  text "45.00mil (1.143mm)" at 4748.7,1901.4 h60
  text "PTH" at 5370.45,1901.4 h60
  text "Round" at 5614.77,1901.4 h60
  text "Top Layer - Bottom Layer" at 5975.11,1901.4 h60
  text "34 Total" at 4431.52,1801.77 h60
  text ".Layer_Name" at -623,-2038.49 h60
M17 Embedded Cavity:
  text ".Layer_Name" at -623,-2038.49 h60
M18 Embedded Assembly:
  text ".Layer_Name" at -623,-2038.49 h60
M19 Embedded Keepout:
  text ".Layer_Name" at -623,-2038.49 h60

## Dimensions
0,375 to 0,-375 on M2 Board Dimensions
-1200,-1580 to -200,-1580 on M2 Board Dimensions
-1100,0 to 1093.75,0 on M2 Board Dimensions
